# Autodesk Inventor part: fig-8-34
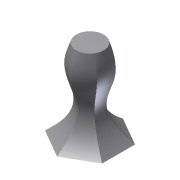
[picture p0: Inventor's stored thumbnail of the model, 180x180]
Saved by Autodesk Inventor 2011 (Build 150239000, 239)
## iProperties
Created: 2007-05
Part Number: fig-8-34
Document SubType Name: Modeling
Designer: Administrator
Density: 1 g/cm^3
Author: Administrator
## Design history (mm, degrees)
sketch "Sketch1"
  geometry: L1 (0, 30)-(25.981, 15); L2 (25.981, 15)-(25.981, -15); L3 (25.981, -15)-(0, -30); L4 (0, -30)-(-25.981, -15); L5 (-25.981, -15)-(-25.981, 15); L6 (-25.981, 15)-(0, 30); 2 further points
  constraints: 12 end point, 1 coincident, 1 vertical, 14 other
workplane "Work Plane1"
sketch "Sketch2"
  geometry: C1 r 12.5 at (0, 0)
  constraints: 1 centre point, 1 other
sketch "Sketch3"
  geometry: L1 (0, 0)-(0, 75)
  constraints: 2 end point, 1 vertical, 1 other
loft "Loft1" sketch "Sketch2", "Sketch3" dims "d5" = 0, "d6" = 90 deg, "d7" = 0, "d8" = 90 deg, "d9" = 0, "d10" = 90 deg, "d11" = 0, "d12" = 0, "d13" = 233.82686, "d14" = 10, "d15" = 75, "d16" = 10, "d17" = 49.08739, "d18" = 10, "d19" = 32.19705, "d20" = 4.29294, "d21" = 35, "d22" = 2.53907, "d23" = 56.85952, "d24" = 7.58127, "d25" = 85, "d26" = 10.45619
body "Solid1"
other parameters: "d1" = 75
